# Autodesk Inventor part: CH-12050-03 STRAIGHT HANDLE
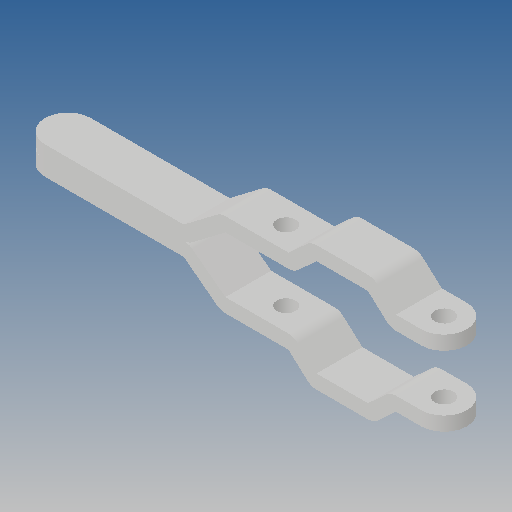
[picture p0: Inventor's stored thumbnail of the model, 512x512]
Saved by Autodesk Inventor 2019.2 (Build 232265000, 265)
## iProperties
Created: 2012-07
Part Number: CH-12050-03 STRAIGHT HANDLE
Material: Ogólny
Document SubType Name: Modeling
Designer: CADENGINEERING4
Density: 1 g/cm^3
Appearance: Domyślna
Author: CADENGINEERING4
Revision Number: ÈÎºÎ
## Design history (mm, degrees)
feature "ÇÐ³ý-À­Éì1"
feature "¾µÏò1"
node "Bryła1"
node "Bryła2"
